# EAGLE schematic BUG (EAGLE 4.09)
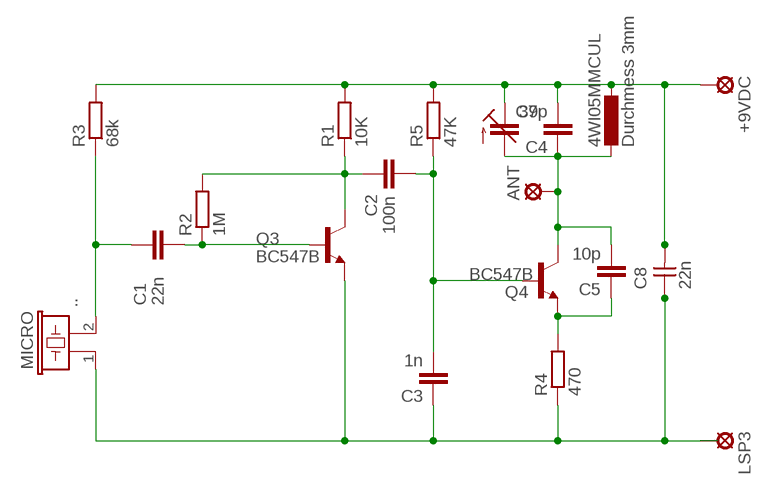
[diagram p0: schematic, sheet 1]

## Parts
4WI05MMCUL  Durchmess 3mm  L-EU0207/10  [0207/10]
+9VDC  SE13  [SE13]
ANT  SE13  [SE13]
C1  22n  C-EU025-025X050  [C025-025X050]
C2  100n  C-EU025-025X050  [C025-025X050]
C3  1n  C-EU025-025X050  [C025-025X050]
C4  39p  C-EU025-025X050  [C025-025X050]
C5  10p  C-EU025-025X050  [C025-025X050]
C7  C-TRIMM808-1  [CTRIM808-1]
C8  22n  CAPNP-10  [C-10]
LSP3  Masse  SE13  [SE13]
MICRO  ..  B/C11S  [B/C11S]
Q3  BC547B  [TO92]
Q4  BC547B  [TO92]
R1  10K  R-EU_R1210W  [R1210W]
R2  1M  R-EU_R1210W  [R1210W]
R3  68k  R-EU_R1210W  [R1210W]
R4  470  R-EU_R1210W  [R1210W]
R5  47K  R-EU_R1210W  [R1210W]

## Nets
MM: C3.1 C8.1 LSP3.MP MICRO.1 Q3.1(E) R4.1
N$2: C1.1 MICRO.2 R3.1
N$5: C1.2 Q3.2(B) R2.1
N$6: C2.1 Q3.3(C) R1.1 R2.2
N$8: 4WI05MMCUL.1 +9VDC.MP C4.2 C7.1(E) C8.2 R1.2 R3.2 R5.2
N$10: C5.1 Q4.1(E) R4.2
N$11: C2.2 C3.2 Q4.2(B) R5.1
N$13: 4WI05MMCUL.2 ANT.MP C4.1 C5.2 C7.2(A) Q4.3(C)

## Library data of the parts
4WI05MMCUL = rcl:L-EU: INDUCTOR, European symbol
+9VDC ANT LSP3 = solpad:SE13: SOLDER PAD
C1-C5 = rcl:C-EU: CAPACITOR, European symbol
C7 = rcl:C-TRIMM: Trimm capacitor
C8 = discrete:CAPNP-10
MICRO = buzzer:B/C11S: BUZZER
Q3 Q4 = transistor-npn:BC547*: NPN Transistor
R1-R5 = rcl:R-EU_: RESISTOR, European symbol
